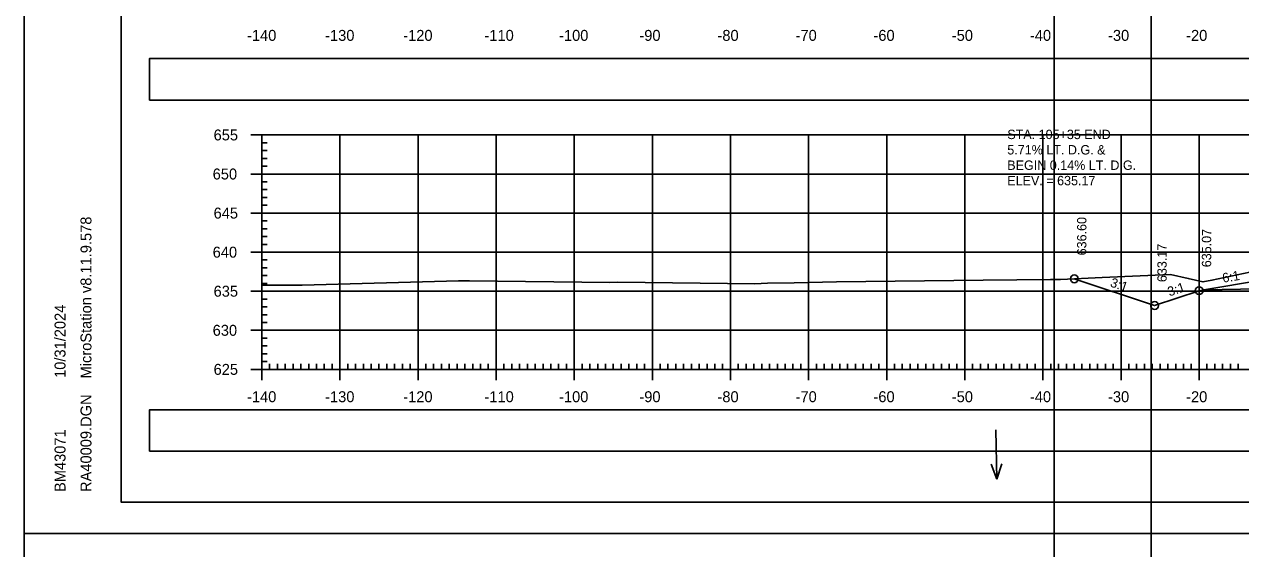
# Model space of a CAD drawing. Extents: x 1381471 to 1382703, y 370300 to 371487.
# Drawn here: x 1381834.4 to 1381990.1, y 370972.4 to 371039.5 of the extents above; entities that cross this region are included whole.
import ezdxf

# ---------------------------------------------------------------- set-up
doc = ezdxf.new("R2010")
doc.units = 0
for name, color, linetype in [('Level 18', 7, 'Continuous'), ('Level 2', 7, 'Continuous'), ('Level 20', 7, 'Continuous'), ('Level 22', 7, 'Continuous'), ('Level 26', 7, 'Continuous'), ('Level 4', 7, 'Continuous'), ('Level 40', 7, 'Continuous'), ('Level 41', 7, 'Continuous'), ('Level 42', 7, 'Continuous'), ('Level 45', 7, 'Continuous'), ('Level 5', 7, 'Continuous'), ('Level 6', 7, 'Continuous')]:
    doc.layers.add(name, color=color, linetype=linetype)

msp = doc.modelspace()

# ---------------------------------------------------------------- linework, layer by layer
at = {"layer": 'Level 18'}
msp.add_lwpolyline([(1381864.77, 371006.06), (1381867.69, 371006.06), (1381869.95, 371006.08), (1381889.94, 371006.62), (1381890.55, 371006.63), (1381891.35, 371006.64), (1381909.31, 371006.42), (1381910.37, 371006.44), (1381927.89, 371006.24), (1381929.52, 371006.32), (1381932.93, 371006.37), (1381938.34, 371006.5), (1381957.11, 371006.72), (1381965.76, 371006.8), (1381967.01, 371006.82), (1381972.37, 371007.04), (1381981.11, 371007.44), (1381983.38, 371006.94), (1381985.26, 371006.5), (1381986.4, 371006.7), (1381991.25, 371007.74)], dxfattribs=at)
at = {"layer": 'Level 2'}
msp.add_lwpolyline([(1381985.39, 371005.47), (1381994.77, 371005.66), (1382004.77, 371005.86), (1382014.77, 371005.66), (1382024.16, 371005.47)], dxfattribs=at)
at = {"layer": 'Level 20'}
msp.add_lwpolyline([(1381968.79, 371006.89), (1381979.07, 371003.47), (1381984.77, 371005.37), (1381985.39, 371005.47), (1381992.77, 371006.7), (1381994.77, 371006.74), (1382004.77, 371006.94), (1382014.77, 371006.74), (1382016.77, 371006.7), (1382024.16, 371005.47), (1382024.77, 371005.37), (1382029.38, 371003.83), (1382035.63, 371005.92)], dxfattribs=at)
at = {"layer": 'Level 22'}
for p, q in [((1381864.77, 371025.3), (1382144.77, 371025.3)), ((1381864.77, 370995.3), (1381864.77, 371025.3)), ((1381874.77, 370995.3), (1381874.77, 371025.3)), ((1381884.77, 370995.3), (1381884.77, 371025.3)), ((1381894.77, 370995.3), (1381894.77, 371025.3)), ((1381904.77, 370995.3), (1381904.77, 371025.3)), ((1381914.77, 370995.3), (1381914.77, 371025.3)), ((1381924.77, 370995.3), (1381924.77, 371025.3)), ((1381934.77, 370995.3), (1381934.77, 371025.3)), ((1381944.77, 370995.3), (1381944.77, 371025.3)), ((1381954.77, 370995.3), (1381954.77, 371025.3)), ((1381964.77, 370995.3), (1381964.77, 371025.3)), ((1381974.77, 370995.3), (1381974.77, 371025.3)), ((1381984.77, 370995.3), (1381984.77, 371025.3)), ((1381864.77, 371020.3), (1382144.77, 371020.3)), ((1381864.77, 371015.3), (1382144.77, 371015.3)), ((1381864.77, 371010.3), (1382144.77, 371010.3)), ((1381864.77, 371005.3), (1382144.77, 371005.3)), ((1381864.77, 371000.3), (1382144.77, 371000.3)), ((1381864.77, 370995.3), (1382144.77, 370995.3))]:
    msp.add_line(p, q, dxfattribs=at)
at = {"layer": 'Level 26'}
for p, q in [((1381834.37, 370974.31), (1382167.7, 370974.31)), ((1381834.37, 370974.3), (1382167.7, 370974.3))]:
    msp.add_line(p, q, dxfattribs=at)
for points in [[(1381834.36, 371187.64), (1382167.7, 371187.64), (1382167.7, 370974.3), (1381834.36, 370974.3)], [(1382080.69, 371183.75), (1382100.31, 371183.75), (1382100.31, 371173.87), (1382116.42, 371173.87), (1382139.62, 371173.87), (1382139.62, 371141.2), (1382162.83, 371141.2), (1382162.95, 370978.29), (1381846.77, 370978.29), (1381846.77, 371183.75)], [(1381834.36, 370974.3), (1382167.7, 370974.3), (1382167.7, 370760.97), (1381834.36, 370760.97)]]:
    msp.add_lwpolyline(points, close=True, dxfattribs=at)
for centre in [(1381968.79, 371006.89), (1381984.77, 371005.37), (1381979.07, 371003.47), (1381979.07, 371003.47)]:
    msp.add_circle(centre, 0.5, dxfattribs=at)
at = {"layer": 'Level 4'}
for p, q in [((1381863.37, 371025.3), (1381866.17, 371025.3)), ((1381864.77, 370995.3), (1381864.77, 371025.3)), ((1381864.77, 371024.3), (1381865.47, 371024.3)), ((1381864.77, 371023.3), (1381865.47, 371023.3)), ((1381864.77, 371022.3), (1381865.47, 371022.3)), ((1381863.37, 371020.3), (1381866.17, 371020.3)), ((1381864.77, 371021.3), (1381865.47, 371021.3)), ((1381864.77, 371019.3), (1381865.47, 371019.3)), ((1381864.77, 371018.3), (1381865.47, 371018.3)), ((1381864.77, 371017.3), (1381865.47, 371017.3)), ((1381864.77, 371016.3), (1381865.47, 371016.3)), ((1381863.37, 371015.3), (1381866.17, 371015.3)), ((1381864.77, 371014.3), (1381865.47, 371014.3)), ((1381864.77, 371013.3), (1381865.47, 371013.3)), ((1381864.77, 371012.3), (1381865.47, 371012.3)), ((1381864.77, 371011.3), (1381865.47, 371011.3)), ((1381863.37, 371010.3), (1381866.17, 371010.3)), ((1381864.77, 371009.3), (1381865.47, 371009.3)), ((1381864.77, 371008.3), (1381865.47, 371008.3)), ((1381864.77, 371007.3), (1381865.47, 371007.3)), ((1381864.77, 371006.3), (1381865.47, 371006.3)), ((1381863.37, 371005.3), (1381866.17, 371005.3)), ((1381864.77, 371004.3), (1381865.47, 371004.3)), ((1381864.77, 371003.3), (1381865.47, 371003.3)), ((1381864.77, 371002.3), (1381865.47, 371002.3)), ((1381863.37, 371000.3), (1381866.17, 371000.3)), ((1381864.77, 371001.3), (1381865.47, 371001.3)), ((1381864.77, 370999.3), (1381865.47, 370999.3)), ((1381864.77, 370998.3), (1381865.47, 370998.3)), ((1381864.77, 370997.3), (1381865.47, 370997.3)), ((1381864.77, 370993.9), (1381864.77, 370996.7)), ((1381864.77, 370996.3), (1381865.47, 370996.3)), ((1381865.77, 370995.3), (1381865.77, 370996)), ((1381866.77, 370995.3), (1381866.77, 370996)), ((1381867.77, 370995.3), (1381867.77, 370996)), ((1381868.77, 370995.3), (1381868.77, 370996)), ((1381869.77, 370995.3), (1381869.77, 370996)), ((1381870.77, 370995.3), (1381870.77, 370996)), ((1381871.77, 370995.3), (1381871.77, 370996)), ((1381872.77, 370995.3), (1381872.77, 370996)), ((1381873.77, 370995.3), (1381873.77, 370996)), ((1381874.77, 370993.9), (1381874.77, 370996.7)), ((1381875.77, 370995.3), (1381875.77, 370996)), ((1381876.77, 370995.3), (1381876.77, 370996)), ((1381877.77, 370995.3), (1381877.77, 370996)), ((1381878.77, 370995.3), (1381878.77, 370996)), ((1381879.77, 370995.3), (1381879.77, 370996)), ((1381880.77, 370995.3), (1381880.77, 370996)), ((1381881.77, 370995.3), (1381881.77, 370996)), ((1381882.77, 370995.3), (1381882.77, 370996)), ((1381883.77, 370995.3), (1381883.77, 370996)), ((1381884.77, 370993.9), (1381884.77, 370996.7)), ((1381885.77, 370995.3), (1381885.77, 370996)), ((1381886.77, 370995.3), (1381886.77, 370996)), ((1381887.77, 370995.3), (1381887.77, 370996)), ((1381888.77, 370995.3), (1381888.77, 370996)), ((1381889.77, 370995.3), (1381889.77, 370996)), ((1381890.77, 370995.3), (1381890.77, 370996)), ((1381891.77, 370995.3), (1381891.77, 370996)), ((1381892.77, 370995.3), (1381892.77, 370996)), ((1381893.77, 370995.3), (1381893.77, 370996)), ((1381894.77, 370993.9), (1381894.77, 370996.7)), ((1381895.77, 370995.3), (1381895.77, 370996)), ((1381896.77, 370995.3), (1381896.77, 370996)), ((1381897.77, 370995.3), (1381897.77, 370996)), ((1381898.77, 370995.3), (1381898.77, 370996)), ((1381899.77, 370995.3), (1381899.77, 370996)), ((1381900.77, 370995.3), (1381900.77, 370996)), ((1381901.77, 370995.3), (1381901.77, 370996)), ((1381902.77, 370995.3), (1381902.77, 370996)), ((1381903.77, 370995.3), (1381903.77, 370996)), ((1381904.77, 370993.9), (1381904.77, 370996.7)), ((1381905.77, 370995.3), (1381905.77, 370996)), ((1381906.77, 370995.3), (1381906.77, 370996)), ((1381907.77, 370995.3), (1381907.77, 370996)), ((1381908.77, 370995.3), (1381908.77, 370996)), ((1381909.77, 370995.3), (1381909.77, 370996)), ((1381910.77, 370995.3), (1381910.77, 370996)), ((1381911.77, 370995.3), (1381911.77, 370996)), ((1381912.77, 370995.3), (1381912.77, 370996)), ((1381913.77, 370995.3), (1381913.77, 370996)), ((1381914.77, 370993.9), (1381914.77, 370996.7)), ((1381915.77, 370995.3), (1381915.77, 370996)), ((1381916.77, 370995.3), (1381916.77, 370996)), ((1381917.77, 370995.3), (1381917.77, 370996)), ((1381918.77, 370995.3), (1381918.77, 370996)), ((1381919.77, 370995.3), (1381919.77, 370996)), ((1381920.77, 370995.3), (1381920.77, 370996)), ((1381921.77, 370995.3), (1381921.77, 370996)), ((1381922.77, 370995.3), (1381922.77, 370996)), ((1381923.77, 370995.3), (1381923.77, 370996)), ((1381924.77, 370993.9), (1381924.77, 370996.7)), ((1381925.77, 370995.3), (1381925.77, 370996)), ((1381926.77, 370995.3), (1381926.77, 370996)), ((1381927.77, 370995.3), (1381927.77, 370996)), ((1381928.77, 370995.3), (1381928.77, 370996)), ((1381929.77, 370995.3), (1381929.77, 370996)), ((1381930.77, 370995.3), (1381930.77, 370996)), ((1381931.77, 370995.3), (1381931.77, 370996)), ((1381932.77, 370995.3), (1381932.77, 370996)), ((1381933.77, 370995.3), (1381933.77, 370996)), ((1381934.77, 370993.9), (1381934.77, 370996.7)), ((1381935.77, 370995.3), (1381935.77, 370996)), ((1381936.77, 370995.3), (1381936.77, 370996)), ((1381937.77, 370995.3), (1381937.77, 370996)), ((1381938.77, 370995.3), (1381938.77, 370996)), ((1381939.77, 370995.3), (1381939.77, 370996)), ((1381940.77, 370995.3), (1381940.77, 370996)), ((1381941.77, 370995.3), (1381941.77, 370996)), ((1381942.77, 370995.3), (1381942.77, 370996)), ((1381943.77, 370995.3), (1381943.77, 370996)), ((1381944.77, 370993.9), (1381944.77, 370996.7)), ((1381945.77, 370995.3), (1381945.77, 370996)), ((1381946.77, 370995.3), (1381946.77, 370996)), ((1381947.77, 370995.3), (1381947.77, 370996)), ((1381948.77, 370995.3), (1381948.77, 370996)), ((1381949.77, 370995.3), (1381949.77, 370996)), ((1381950.77, 370995.3), (1381950.77, 370996)), ((1381951.77, 370995.3), (1381951.77, 370996)), ((1381952.77, 370995.3), (1381952.77, 370996)), ((1381953.77, 370995.3), (1381953.77, 370996)), ((1381954.77, 370993.9), (1381954.77, 370996.7)), ((1381955.77, 370995.3), (1381955.77, 370996)), ((1381956.77, 370995.3), (1381956.77, 370996)), ((1381957.77, 370995.3), (1381957.77, 370996)), ((1381958.77, 370995.3), (1381958.77, 370996)), ((1381959.77, 370995.3), (1381959.77, 370996)), ((1381960.77, 370995.3), (1381960.77, 370996)), ((1381961.77, 370995.3), (1381961.77, 370996)), ((1381962.77, 370995.3), (1381962.77, 370996)), ((1381963.77, 370995.3), (1381963.77, 370996)), ((1381964.77, 370993.9), (1381964.77, 370996.7)), ((1381965.77, 370995.3), (1381965.77, 370996)), ((1381966.77, 370995.3), (1381966.77, 370996)), ((1381967.77, 370995.3), (1381967.77, 370996)), ((1381968.77, 370995.3), (1381968.77, 370996)), ((1381969.77, 370995.3), (1381969.77, 370996)), ((1381970.77, 370995.3), (1381970.77, 370996)), ((1381971.77, 370995.3), (1381971.77, 370996)), ((1381972.77, 370995.3), (1381972.77, 370996)), ((1381973.77, 370995.3), (1381973.77, 370996)), ((1381974.77, 370993.9), (1381974.77, 370996.7)), ((1381975.77, 370995.3), (1381975.77, 370996)), ((1381976.77, 370995.3), (1381976.77, 370996)), ((1381977.77, 370995.3), (1381977.77, 370996)), ((1381978.77, 370995.3), (1381978.77, 370996)), ((1381979.77, 370995.3), (1381979.77, 370996)), ((1381980.77, 370995.3), (1381980.77, 370996)), ((1381981.77, 370995.3), (1381981.77, 370996)), ((1381982.77, 370995.3), (1381982.77, 370996)), ((1381983.77, 370995.3), (1381983.77, 370996)), ((1381984.77, 370993.9), (1381984.77, 370996.7)), ((1381985.77, 370995.3), (1381985.77, 370996)), ((1381986.77, 370995.3), (1381986.77, 370996)), ((1381987.77, 370995.3), (1381987.77, 370996)), ((1381988.77, 370995.3), (1381988.77, 370996)), ((1381989.77, 370995.3), (1381989.77, 370996)), ((1381863.37, 370995.3), (1381866.17, 370995.3)), ((1381864.77, 370995.3), (1382144.77, 370995.3))]:
    msp.add_line(p, q, dxfattribs=at)
at = {"layer": 'Level 40'}
for p, q in [((1381958.75, 370987.55), (1381958.87, 370981.27)), ((1381958.87, 370981.27), (1381958.13, 370983.18)), ((1381958.87, 370981.27), (1381959.53, 370983.21))]:
    msp.add_line(p, q, dxfattribs=at)
at = {"layer": 'Level 45'}
msp.add_line((1381978.61, 370851.12), (1381978.61, 371056.58), dxfattribs=at)
for points in [[(1381966.21, 371060.47), (1382299.55, 371060.47), (1382299.55, 370847.14), (1381966.21, 370847.14)], [(1382212.53, 371056.58), (1382232.15, 371056.58), (1382232.15, 371046.7), (1382248.27, 371046.7), (1382271.46, 371046.7), (1382271.46, 371022.37), (1382294.79, 371022.37), (1382294.79, 370851.12), (1381978.61, 370851.12), (1381978.61, 371056.58)]]:
    msp.add_lwpolyline(points, close=True, dxfattribs=at)
at = {"layer": 'Level 6'}
for p, q in [((1381846.77, 370978.29), (1381846.77, 371183.75)), ((1381846.77, 370978.29), (1381846.77, 370978.29)), ((1382162.95, 370978.29), (1381846.77, 370978.29))]:
    msp.add_line(p, q, dxfattribs=at)
for points in [[(1381850.41, 371029.76), (1382159.14, 371029.76), (1382159.14, 371035.09), (1381850.41, 371035.09)], [(1381850.41, 370984.82), (1382159.14, 370984.82), (1382159.14, 370990.14), (1381850.41, 370990.14)]]:
    msp.add_lwpolyline(points, close=True, dxfattribs=at)

# ---------------------------------------------------------------- texts
at = {"layer": 'Level 41'}
for s, p in [('636.60', (1381970.34, 371009.89)), ('635.07', (1381986.32, 371008.37)), ('633.17', (1381980.62, 371006.47))]:
    msp.add_text(s, height=1.2, rotation=90, dxfattribs=at).set_placement(p)
at = {"layer": 'Level 42'}
for s, rotation, p in [('6:1', 9.4623, (1381987.84, 371006.39)), ('3:1', 341.5651, (1381973.3, 371005.92)), ('3:1', 18.4349, (1381980.97, 371004.63))]:
    msp.add_text(s, height=1.2, rotation=rotation, dxfattribs=at).set_placement(p)
at = {"layer": 'Level 5'}
for s, height, p in [('-140', 1.4, (1381862.88, 371037.34)), ('-130', 1.4, (1381872.88, 371037.34)), ('-120', 1.4, (1381882.88, 371037.34)), ('-110', 1.4, (1381893.28, 371037.34)), ('-100', 1.4, (1381902.83, 371037.34)), ('-90', 1.4, (1381913.11, 371037.34)), ('-80', 1.4, (1381923.11, 371037.34)), ('-70', 1.4, (1381933.11, 371037.34)), ('-60', 1.4, (1381943.08, 371037.34)), ('-50', 1.4, (1381953.11, 371037.34)), ('-40', 1.4, (1381963.11, 371037.34)), ('-30', 1.4, (1381973.11, 371037.34)), ('-20', 1.4, (1381983.11, 371037.34)), ('655', 1.4, (1381858.6, 371024.6)), ('STA. 105+35 END', 1.2, (1381960.21, 371024.77)), ('5.71% LT. D.G. &', 1.2, (1381960.21, 371022.8)), ('BEGIN 0.14% LT. D.G.', 1.2, (1381960.21, 371020.83)), ('650', 1.4, (1381858.48, 371019.6)), ('ELEV. = 635.17', 1.2, (1381960.21, 371018.86)), ('645', 1.4, (1381858.6, 371014.6)), ('640', 1.4, (1381858.48, 371009.6)), ('635', 1.4, (1381858.6, 371004.6)), ('630', 1.4, (1381858.48, 370999.6)), ('625', 1.4, (1381858.6, 370994.6)), ('-140', 1.4, (1381862.88, 370991.1)), ('-130', 1.4, (1381872.88, 370991.1)), ('-120', 1.4, (1381882.88, 370991.1)), ('-110', 1.4, (1381893.28, 370991.1)), ('-100', 1.4, (1381902.83, 370991.1)), ('-90', 1.4, (1381913.11, 370991.1)), ('-80', 1.4, (1381923.11, 370991.1)), ('-70', 1.4, (1381933.11, 370991.1)), ('-60', 1.4, (1381943.08, 370991.1)), ('-50', 1.4, (1381953.11, 370991.1)), ('-40', 1.4, (1381963.11, 370991.1)), ('-30', 1.4, (1381973.11, 370991.1)), ('-20', 1.4, (1381983.11, 370991.1))]:
    msp.add_text(s, height=height, dxfattribs=at).set_placement(p)
at = {"layer": 'Level 6'}
for s, p in [('MicroStation v8.11.9.578', (1381842.96, 370994.14)), ('10/31/2024', (1381839.64, 370994.21)), ('RA40009.DGN', (1381842.96, 370979.61)), ('BM43071', (1381839.64, 370979.61))]:
    msp.add_text(s, height=1.4, rotation=90, dxfattribs=at).set_placement(p)

doc.saveas('drawing.dxf')
